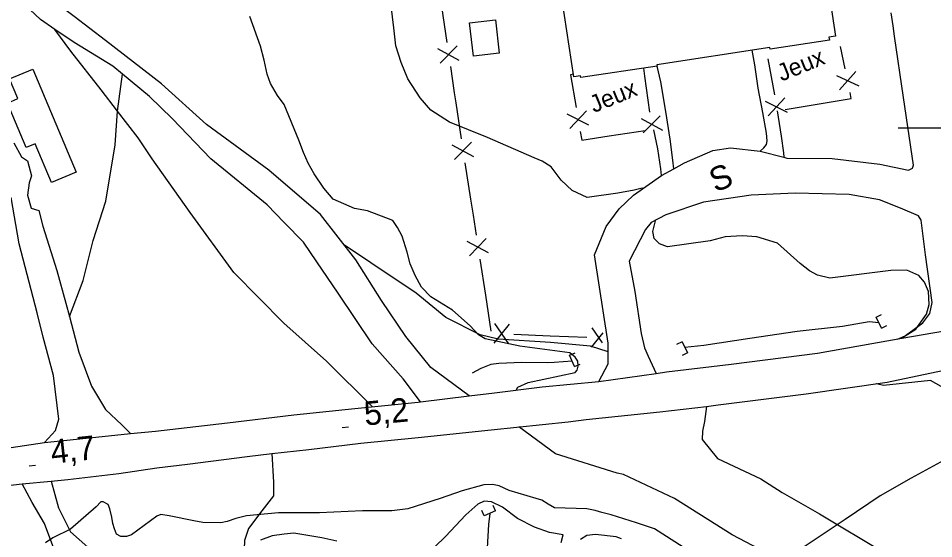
# Model space of a CAD drawing. Extents: x 362852 to 366875, y 5563573 to 5566479.
# Drawn here: x 364445.4 to 364595.8, y 5564732.5 to 5564818 of the extents above; entities that cross this region are included whole.
import ezdxf

# ---------------------------------------------------------------- set-up
doc = ezdxf.new("R2010")
doc.units = 0
for name, color, linetype in [('Niveau 19', 7, 'Continuous'), ('Niveau 2', 7, 'Continuous'), ('Niveau 21', 7, 'Continuous'), ('Niveau 22', 7, 'Continuous'), ('Niveau 26', 7, 'Continuous'), ('Niveau 3', 7, 'Continuous'), ('Niveau 31', 7, 'Continuous'), ('Niveau 37', 7, 'Continuous'), ('Niveau 4', 7, 'Continuous'), ('Niveau 52', 7, 'Continuous'), ('Niveau 56', 7, 'Continuous'), ('Niveau 61', 7, 'Continuous')]:
    doc.layers.add(name, color=color, linetype=linetype)

msp = doc.modelspace()

# ---------------------------------------------------------------- linework, layer by layer
at = {"layer": 'Niveau 19'}
for points in [[(364519.5, 5564755.95), (364513.2, 5564760.6), (364509.08, 5564765.71), (364505.07, 5564771.65), (364500.87, 5564778.34), (364495.07, 5564785.79), (364486.59, 5564793.06), (364476.35, 5564800.55), (364468.92, 5564807.23), (364459.76, 5564814.37), (364454.6, 5564818.27), (364453.03, 5564819.46), (364446.52, 5564826.2), (364439.4, 5564834)], [(364511.49, 5564754.98), (364508.67, 5564758.76), (364503.54, 5564764.53), (364497.95, 5564772.82), (364494.44, 5564777.99), (364492.27, 5564781.22), (364489.09, 5564784.45), (364486.31, 5564787.35), (364477.02, 5564794.93), (364470.68, 5564801.54), (364466.99, 5564805.14), (364462.51, 5564808.83), (364460.93, 5564810.13), (364454.58, 5564814), (364451.41, 5564816.17), (364449.07, 5564817.78), (364443.74, 5564822.83)], [(364444.67, 5564797.54), (364445.91, 5564795.25), (364446.91, 5564794.61), (364447.59, 5564792.14), (364447.19, 5564790.98), (364446.9, 5564788.94), (364447.5, 5564786.81), (364448.79, 5564786.4), (364449.44, 5564783.86), (364451.75, 5564776.57), (364453.23, 5564771.18), (364453.81, 5564768.99), (364455.35, 5564763.12), (364457.41, 5564757.56), (364459.72, 5564753.72), (364462.43, 5564751.18), (364463.86, 5564749.77)], [(364449.73, 5564748.29), (364451.54, 5564750.26), (364452.07, 5564752.15), (364451.17, 5564759.3), (364449.5, 5564765.59), (364448.51, 5564769.61), (364445.56, 5564780.95), (364444.24, 5564788.58)]]:
    msp.add_lwpolyline(points, dxfattribs=at)
at = {"layer": 'Niveau 2'}
for points in [[(364548.05, 5564790.02), (364547.94, 5564790.07), (364546.58, 5564789.76), (364543.91, 5564789.29), (364538.86, 5564788.58), (364536.42, 5564789.7), (364534.6, 5564791.43), (364532.98, 5564793.62), (364531.5, 5564794.51), (364530.16, 5564795.07), (364522.49, 5564798.39), (364516.25, 5564800.93), (364513.21, 5564802.91), (364511.42, 5564804.91), (364509.4, 5564808.06), (364508.33, 5564810.72), (364507.46, 5564813.47), (364507.13, 5564816.44), (364505.49, 5564830.05)], [(364527.19, 5564756.89), (364527.2, 5564756.91), (364527.5, 5564757.41), (364529.19, 5564758.16), (364536.9, 5564759.83), (364537.24, 5564760.21), (364537.42, 5564760.85), (364537.34, 5564761.68), (364536.9, 5564762.31), (364536.05, 5564763.02), (364527.83, 5564764.13), (364522.13, 5564765.33), (364521.04, 5564766.01), (364519.64, 5564767.49), (364516.75, 5564770.03), (364513.18, 5564772.24), (364511.68, 5564773.8), (364510.6, 5564775.72), (364509.82, 5564777.64), (364509.28, 5564779.59), (364508.49, 5564782.19), (364507.72, 5564783.61), (364506.94, 5564784.78), (364502.76, 5564786.37), (364500.67, 5564786.76), (364497.13, 5564788.29), (364495.6, 5564790.09), (364494.03, 5564792.43), (364493.01, 5564794.19), (364492.25, 5564795.93), (364491.48, 5564797.98), (364489.11, 5564803.85), (364488.02, 5564805.32), (364486.86, 5564807.27), (364486.29, 5564808.84), (364485.8, 5564811.13), (364485.18, 5564813.43), (364483.45, 5564818.32)], [(364589.87, 5564765.29), (364591.12, 5564765.84), (364592.9, 5564766.95), (364594.62, 5564769.41), (364595.09, 5564770.97), (364594.94, 5564773.14), (364594.33, 5564774.63), (364593.38, 5564775.73), (364591.38, 5564776.64), (364588.8, 5564776.57), (364578.77, 5564775.28), (364576.7, 5564775.79), (364575.41, 5564776.5), (364573.9, 5564777.74), (364570.17, 5564781.05), (364566.75, 5564782.12), (364564.34, 5564782.24), (364561.55, 5564782.08), (364559.08, 5564781.43), (364552.06, 5564780.46), (364550.76, 5564780.92), (364549.9, 5564781.81), (364549.69, 5564782.96), (364550.09, 5564784.74), (364550.12, 5564784.83)], [(364595.28, 5564758.49), (364587.55, 5564757.65), (364586.43, 5564757.94), (364586.39, 5564757.96)], [(364597.06, 5564757.49), (364595.28, 5564758.49)], [(364600.72, 5564710.27), (364593.96, 5564712.18), (364584.52, 5564718.6), (364574.3, 5564726.76), (364571.67, 5564728.41), (364562.72, 5564733.12), (364553.22, 5564739.11), (364544.86, 5564743.02), (364543.83, 5564743.28), (364533.66, 5564746.45), (364527.67, 5564750.86)], [(364556.03, 5564730.23), (364549.92, 5564734.13), (364548.13, 5564734.7), (364546.97, 5564735.1), (364542.84, 5564736.4), (364541.3, 5564736.82), (364540.19, 5564737.11), (364538.82, 5564737.42), (364533.53, 5564737.56), (364532.47, 5564738.19), (364531.41, 5564738.81), (364530.48, 5564739.11), (364526.04, 5564740.41), (364524.42, 5564741.18), (364523.33, 5564741.41), (364521.92, 5564741.34), (364518.33, 5564740.37), (364514.74, 5564739.08), (364509.39, 5564737.39), (364506.78, 5564737.07), (364501.98, 5564737.1), (364494.9, 5564736.75), (364488.18, 5564736.74), (364482.9, 5564736.26), (364481.15, 5564735.8), (364479.72, 5564735.33), (364478.7, 5564735.1), (364475.75, 5564735.14), (364474.25, 5564735.46), (364470.21, 5564736.23), (364468.81, 5564736.47), (364468.17, 5564736.21), (364463.99, 5564733.13), (364463.17, 5564732.86), (364462.24, 5564732.85), (364461.57, 5564733.26), (364461.23, 5564734.12), (364460.94, 5564734.99), (364460.76, 5564736.04), (364460.46, 5564737.41), (364460.18, 5564738.1), (364459.36, 5564738.58), (364458.95, 5564738.53), (364458.21, 5564737.73), (364453.97, 5564734.07), (364451.06, 5564732.63), (364449.89, 5564731.84)], [(364534.62, 5564731.86), (364534.91, 5564733.16), (364532.71, 5564733.51), (364530.22, 5564734.42), (364527.41, 5564735.83), (364524.98, 5564737.7), (364523.18, 5564738.58), (364521.97, 5564738.65), (364520.93, 5564738.16), (364518.95, 5564736.41), (364515.58, 5564732.86), (364513.84, 5564731.15)], [(364497.75, 5564732.1), (364495.28, 5564732.65), (364490.68, 5564733.39), (364489.12, 5564733.25), (364487.11, 5564732.98), (364485.21, 5564732.27)], [(364544.53, 5564732.49), (364543.65, 5564732.81), (364540.27, 5564733.17), (364538.83, 5564733.02), (364537.79, 5564732.35)]]:
    msp.add_lwpolyline(points, dxfattribs=at)
at = {"layer": 'Niveau 21'}
for points in [[(364440.92, 5564747.01), (364449.73, 5564748.29), (364460.23, 5564749.42), (364463.86, 5564749.77), (364467.96, 5564750.17), (364479.79, 5564751.55), (364490.66, 5564752.84), (364500.7, 5564753.88), (364511.1, 5564754.93), (364511.49, 5564754.98), (364519.5, 5564755.95), (364523.67, 5564756.45), (364531.48, 5564757.43), (364540.82, 5564758.35), (364550.22, 5564759.66), (364551.9, 5564759.9), (364562.54, 5564761.15), (364576.72, 5564762.98), (364590.59, 5564765.42), (364603.01, 5564767.56)], [(364437.44, 5564740.54), (364446.06, 5564741.52), (364450.81, 5564741.96), (364453.56, 5564742.21), (364461.93, 5564743.22), (364468.15, 5564744.16), (364473.2, 5564744.75), (364483.01, 5564746.03), (364487.08, 5564746.48), (364493.14, 5564747.16), (364501.69, 5564748.19), (364511.13, 5564749.14), (364523.13, 5564750.39), (364535.78, 5564751.71), (364538.73, 5564752.08), (364550.83, 5564753.36), (364558.46, 5564754.24), (364560.38, 5564754.47), (364574.86, 5564756.28), (364588.16, 5564758.22), (364598.32, 5564760.36)]]:
    msp.add_lwpolyline(points, dxfattribs=at)
at = {"layer": 'Niveau 22'}
for points in [[(364503.6, 5564754.17), (364496.03, 5564761.65), (364489.02, 5564767.92), (364480.82, 5564776.21), (364473.66, 5564786.09), (364467.42, 5564794.93), (364465.08, 5564798.38), (364461.72, 5564802.77), (364459.05, 5564806.24), (364454.05, 5564812.6), (364451.41, 5564816.17)], [(364567.31, 5564796.15), (364567.93, 5564796.7), (364568.32, 5564797.25), (364568.46, 5564797.88), (364568.34, 5564799.15), (364567.72, 5564802.5), (364566.99, 5564806.54), (364566.41, 5564810.38), (364566.01, 5564812.75)], [(364553.1, 5564793.26), (364552.98, 5564794.7), (364552.49, 5564798.17), (364551.8, 5564802.67), (364550.97, 5564807.59), (364550.37, 5564810.16)], [(364453.81, 5564768.99), (364456.06, 5564774.92), (364457.7, 5564781.52), (364459.79, 5564787.93), (364461.33, 5564797.21), (364461.72, 5564802.77), (364462.51, 5564808.83)], [(364570.11, 5564802.78), (364570.73, 5564798.63), (364571.16, 5564795.89), (364571.19, 5564795.17)], [(364551.07, 5564792.15), (364550.99, 5564793.28), (364550.49, 5564796.58), (364549.84, 5564799.7)], [(364542.33, 5564763.2), (364539.4, 5564764.14), (364532.88, 5564764.73), (364524.28, 5564765.26), (364521.32, 5564765.97), (364515.63, 5564768.83), (364510.77, 5564772.86), (364503.36, 5564777.81), (364499.01, 5564780.73)], [(364558.46, 5564754.24), (364558.14, 5564751.78), (364557.81, 5564750.18), (364557.77, 5564748.78), (364560.28, 5564745.7), (364567.41, 5564742.31), (364570.94, 5564740.08), (364577.05, 5564736.59), (364580.6, 5564734.47), (364587.94, 5564730.09), (364594.24, 5564725.38), (364603.92, 5564719.56)], [(364487.08, 5564746.48), (364487.36, 5564741.77), (364487.33, 5564739.53), (364485.43, 5564737.06), (364483.23, 5564734.15), (364482.57, 5564732.19), (364482.54, 5564730.81), (364482.99, 5564728.29), (364482.87, 5564726.98), (364482.07, 5564725.06), (364481.54, 5564723.89)], [(364452.22, 5564717.84), (364452.04, 5564720.99), (364452.23, 5564723.03), (364452.19, 5564725.8), (364452.18, 5564727.5), (364451.7, 5564729.26), (364451.07, 5564731.35), (364449.71, 5564734.98), (364447.71, 5564738.43), (364446.06, 5564741.52)], [(364450.81, 5564741.96), (364452.03, 5564737.55), (364453.96, 5564733.64), (364456.86, 5564731.11), (364460.14, 5564728.73), (364463.62, 5564725.96), (364465.45, 5564724.26), (364466.69, 5564722.54), (364468.61, 5564719.92)]]:
    msp.add_lwpolyline(points, dxfattribs=at)
at = {"layer": 'Niveau 26'}
for p, q in [((364586.35, 5564768.91), (364587.26, 5564769.34)), ((364587.24, 5564767.09), (364586.35, 5564768.91)), ((364587.24, 5564767.09), (364588.14, 5564767.54)), ((364554.49, 5564764.83), (364553.58, 5564764.4)), ((364554.49, 5564764.83), (364555.38, 5564763.01)), ((364536, 5564762.63), (364536.92, 5564763.02)), ((364536.79, 5564760.77), (364536, 5564762.63)), ((364555.38, 5564763.01), (364554.47, 5564762.58)), ((364536.79, 5564760.77), (364537.71, 5564761.17)), ((364523.81, 5564737.09), (364523.41, 5564737.98)), ((364521.98, 5564736.24), (364521.57, 5564737.15)), ((364523.81, 5564737.09), (364521.98, 5564736.24))]:
    msp.add_line(p, q, dxfattribs=at)
at = {"layer": 'Niveau 3'}
for p, q in [((364498.65, 5564750.78), (364499.68, 5564750.88)), ((364447.18, 5564744.45), (364448.21, 5564744.57))]:
    msp.add_line(p, q, dxfattribs=at)
at = {"layer": 'Niveau 31'}
for points in [[(364534.4, 5564823.55), (364563.18, 5564827.91), (364562.76, 5564830.71), (364576.99, 5564832.86), (364579.69, 5564815.05), (364578.61, 5564814.89), (364578.69, 5564814.41), (364568.95, 5564812.94), (364568.91, 5564813.19), (364550.34, 5564810.38), (364550.37, 5564810.16), (364537.83, 5564808.26), (364537.79, 5564808.56), (364536.69, 5564808.39), (364534.4, 5564823.55)], [(364523.81, 5564817.73), (364524.44, 5564812.28), (364520.2, 5564811.79), (364519.57, 5564817.24), (364523.81, 5564817.73)], [(364447.77, 5564809.63), (364454.91, 5564792.74), (364450.88, 5564791.04), (364448.2, 5564797.38), (364446.71, 5564796.75), (364443.61, 5564804.08), (364445.32, 5564804.81), (364443.96, 5564808.03), (364447.77, 5564809.63)]]:
    msp.add_lwpolyline(points, dxfattribs=at)
at = {"layer": 'Niveau 37'}
for p, q in [((364514.95, 5564819.95), (364515.82, 5564814.01)), ((364517.51, 5564813.46), (364514.7, 5564810.62)), ((364581.26, 5564809.72), (364580.5, 5564813.39)), ((364517.86, 5564811.08), (364514.35, 5564812.99)), ((364568.59, 5564811.32), (364569.64, 5564805.41)), ((364548.37, 5564808.5), (364548.19, 5564809.83)), ((364579.87, 5564808.61), (364583.49, 5564806.91)), ((364580.35, 5564806.26), (364583, 5564809.26)), ((364549.2, 5564802.56), (364548.37, 5564808.5)), ((364517.28, 5564804.12), (364518.17, 5564798.19)), ((364571.77, 5564802.55), (364568.2, 5564804.35)), ((364571.35, 5564804.91), (364568.62, 5564801.99)), ((364538.76, 5564802.82), (364536.02, 5564799.91)), ((364571.42, 5564803), (364577.33, 5564804)), ((364539.17, 5564800.45), (364535.61, 5564802.27)), ((364547.73, 5564801.54), (364551.23, 5564799.61)), ((364548.06, 5564799.17), (364550.9, 5564801.98)), ((364542.5, 5564798.67), (364548.43, 5564799.58)), ((364520.23, 5564795.26), (364516.7, 5564797.16)), ((364519.87, 5564797.64), (364517.06, 5564794.79)), ((364518.77, 5564794.23), (364519.72, 5564788.31)), ((364522.31, 5564781.83), (364519.52, 5564778.97)), ((364522.68, 5564779.46), (364519.15, 5564781.34)), ((364521.22, 5564778.42), (364522.15, 5564772.49)), ((364522.15, 5564772.49), (364523.07, 5564766.57)), ((364526.07, 5564767.73), (364523.54, 5564764.64)), ((364523.67, 5564767.83), (364525.94, 5564764.54)), ((364539.66, 5564767.16), (364541.37, 5564764.67)), ((364526.81, 5564766.1), (364532.8, 5564765.85)), ((364532.8, 5564765.85), (364538.8, 5564765.6)), ((364541.43, 5564766.3), (364539.53, 5564763.96))]:
    msp.add_line(p, q, dxfattribs=at)
for points in [[(364516.4, 5564810.06), (364517.03, 5564805.75), (364517.28, 5564804.12)], [(364536.63, 5564808.82), (364536.12, 5564808.73), (364537.05, 5564803.33)], [(364577.33, 5564804), (364582.28, 5564804.84), (364582.08, 5564805.8)], [(364537.74, 5564799.39), (364537.98, 5564797.98), (364542.5, 5564798.67)], [(364519.72, 5564788.31), (364520.15, 5564785.65), (364520.63, 5564782.38)]]:
    msp.add_lwpolyline(points, dxfattribs=at)
at = {"layer": 'Niveau 4'}
for points in [[(364586.81, 5564767.99), (364585.21, 5564768.15), (364580.81, 5564767.38), (364573.39, 5564766.52), (364565.59, 5564765.39), (364558.03, 5564764.25), (364554.92, 5564763.93)], [(364536.4, 5564761.69), (364533.47, 5564761.47), (364532.37, 5564761.41), (364528.16, 5564761.44), (364524.37, 5564761.28), (364523.03, 5564761.12), (364521.41, 5564760.45), (364519.96, 5564759.72)], [(364603.58, 5564748.56), (364598.15, 5564745.74), (364592.12, 5564742.42), (364587.02, 5564739.56), (364581.29, 5564735.68), (364574.85, 5564731.38), (364572.5, 5564729.55), (364568.86, 5564724.55), (364566.92, 5564720.38), (364566.92, 5564718.59), (364565.47, 5564716.84), (364563.77, 5564714.9)], [(364522.91, 5564736.66), (364522.66, 5564734.83), (364522.32, 5564729.07), (364522.82, 5564726.89), (364524.59, 5564721.42), (364527.03, 5564711.55)]]:
    msp.add_lwpolyline(points, dxfattribs=at)
at = {"layer": 'Niveau 52'}
for points in [[(364540.82, 5564758.35), (364542.35, 5564761.23), (364542.32, 5564764.61), (364540.11, 5564779.13), (364541.98, 5564783.79), (364544.13, 5564786.7), (364546.5, 5564788.93), (364551.07, 5564792.15), (364553.1, 5564793.26), (364554.87, 5564794.23), (364559.5, 5564796.26), (364562.42, 5564796.73), (364567.31, 5564796.15), (364571.19, 5564795.17), (364571.68, 5564795.04), (364579.12, 5564794.95), (364586.96, 5564794.02), (364591.65, 5564793.04), (364592.32, 5564793.37), (364592.48, 5564793.88), (364590.87, 5564805.01), (364589.38, 5564815.08), (364589.15, 5564816.78), (364588.85, 5564818.91)], [(364590.59, 5564765.42), (364594.02, 5564767.94), (364595.19, 5564769.48), (364595.55, 5564771.3), (364594.48, 5564779.14), (364593.73, 5564784.86), (364593.32, 5564785.56), (364590.37, 5564786.83), (364586.89, 5564788.18), (364581.93, 5564789.06), (364573.08, 5564789.27), (364565.82, 5564788.94), (364557.97, 5564787.79), (364551.81, 5564785.72), (364549.41, 5564784.46), (364548.46, 5564783.3), (364545.77, 5564778.09), (364546.7, 5564773.12), (364547.74, 5564766.24), (364548.3, 5564763.85), (364548.92, 5564762.49), (364550.22, 5564759.66)]]:
    msp.add_lwpolyline(points, dxfattribs=at)
at = {"layer": 'Niveau 61'}
msp.add_line((364590, 5564800), (364610, 5564800), dxfattribs=at)

# ---------------------------------------------------------------- texts
at = {"layer": 'Niveau 3'}
for s, rotation, p in [('5,2  ', 5.5086, (364502.4, 5564751.08)), ('4,7  ', 6.1685, (364450.93, 5564744.8))]:
    msp.add_text(s, height=3.93, rotation=rotation, dxfattribs=at).set_placement(p)
at = {"layer": 'Niveau 52'}
msp.add_text('S', height=3.93, rotation=22.09, dxfattribs=at).set_placement((364559.94, 5564789.35))
at = {"layer": 'Niveau 56'}
for p in [(364570.81, 5564807.59), (364539.98, 5564802.42)]:
    msp.add_text('Jeux', height=2.81, rotation=22.09, dxfattribs=at).set_placement(p)

doc.saveas('drawing.dxf')
